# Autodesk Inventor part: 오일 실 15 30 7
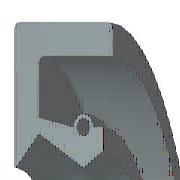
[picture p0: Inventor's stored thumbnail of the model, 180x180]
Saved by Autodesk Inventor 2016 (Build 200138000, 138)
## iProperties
IsCustomPart: 1
Created: 2012-02
Part Number: 오일 실 15 30 7
Material: 고무
Description: 오일-실
Document SubType Name: Modeling
Standard: KS B 2804
Designer: mduedu
Standards Organization: KS
Language: ko-KR
Size Designation: D - 15 30 7
Categories: <MemberInstance><Categories><Category DisplayName="샤프트 부품" InternalName="7f7aeb1f-a693-4053-b835-cee3144e0d98" Mnemonic="SHFT"><Category DisplayName="실링" Intern
Density: 0.93 g/cm^3
Appearance: 고무 - 검은색 - 버전 1.1
Author: mduedu
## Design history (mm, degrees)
revolve "본체" stored, may be unused: angle "d17" = 90 deg
revolve "스프링1" stored, may be unused: angle "d18" = 90 deg
body "Solid1"
sketch "스케치1"
  geometry: L1 (0, 15)-(7, 15); L2 (7, 13.25)-(1.75, 13.25); L3 (1.75, 9.25)-(4.9, 7.5); L4 (4.9, 7.5)-(0, 7.5); L5 (0, 0)-(9.586, 0) reference; L6 (4.9, 7.5)-(6.3, 8.375); L7 (0, 18)-(0, -3) reference; L8 (-1.941, 0)-(11.507, 0) reference; L9 (4.2, 9.6)-(1.75, 10.09); L10 (1.75, 10.09)-(1.75, 13.25); L11 (0, 15)-(0, 7.588); L12 (4.9, 7.5)-(0, 7.5); L13 (1.75, 9.25)-(0.152, 7.528); L14 (7, 15)-(7, 13.25); L15 (5.6, 9.6)-(6.3, 9.6); L16 (6.3, 9.6)-(6.3, 8.375); C1 r 0.455 at (4.9, 9.6); A1 r 0.7 centre (4.9, 9.6) between (5.6, 9.6) and (4.2, 9.6); A2 r 0.088 centre (0.088, 7.588) between (0, 7.588) and (0.152, 7.528); 1 further point
  constraints: 28 end point, 5 horizontal alignment, 5 point on line, 4 point on circle, 4 vertical alignment, 3 centre point, 3 tangent, 2 collinear, 2 horizontal, 2 perpendicular, 1 coincident, 1 parallel
  dimensions: "d0" = 30 diameter of L1 L5 (= SD2); "d1" = 1.75 distance of L1.end L2.start (= SD); "d2" = 0.91 diameter of C1 (= SPDI); "d3" = 1.4 diameter of A1 (= SPDA); "d4" = 15 diameter of L3.end L5 (= NND); "d5" = 18.5 diameter of L3.start L5 (= TKDM); "d7" = 20.18 diameter of L9.end L5 (= TKDM + 0.24 x SWDT); "d8" = 1.75 distance between parallel lines of L11 L10 (= SD); "d9" = 4.9 distance from line of L11 C1.centre (= SPDST); "d10" = 19.2 diameter of C1.centre L5 (= HLDM); "d11" = 0.0875 radius of A2 (= 0.25 x LAB); "d12" = 6.3 distance between parallel lines of L11 L16 (= SDI); "d13" = 16.75 diameter of L6.end L5 (= ABDM); "d14" = 7 distance from line of L11 L1.end (= SWDT)
fillet "모깎기1" dims "d6" = 0.3 (= RR)
other parameters: "SD2" = 30 [user parameter; used in 1 equation term], "SWDT" = 7 [user parameter; used in 2 equation terms], "RR" = 0.3 [user parameter; used in 1 equation term], "SD" = 1.75 [user parameter; used in 2 equation terms], "NND" = 15 [user parameter; used in 1 equation term], "SPDA" = 1.4 [user parameter; used in 1 equation term], "SPDI" = 0.91 [user parameter; used in 1 equation term], "TKDM" = 18.5 [user parameter; used in 2 equation terms], "HLDM" = 19.2 [user parameter; used in 1 equation term], "ABDM" = 16.75 [user parameter; used in 1 equation term], "SDI" = 6.3 [user parameter; used in 1 equation term], "SPDST" = 4.9 [user parameter; used in 1 equation term], "LAB" = 0.35 [user parameter; used in 1 equation term], "d15" = 0, "d16" = 0, "d19" = 0
